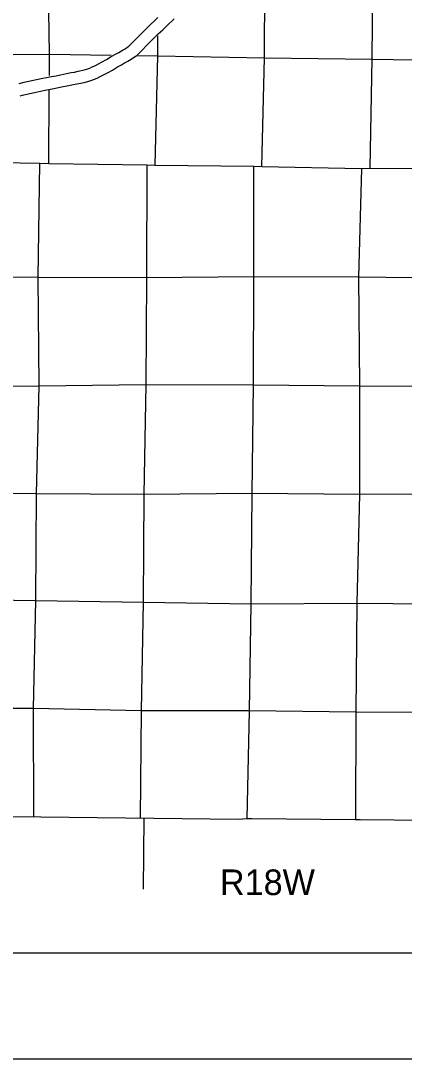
# Model space of a CAD drawing. Extents: x 369523 to 838377, y 495025 to 936819.
# Drawn here: x 611048 to 630067, y 495025 to 546526 of the extents above; entities that cross this region are included whole.
import ezdxf

# ---------------------------------------------------------------- set-up
doc = ezdxf.new("R2010")
doc.units = 0
for name, color, linetype in [('21', 7, 'Continuous'), ('Level 11', 7, 'Continuous'), ('Level 15', 7, 'Continuous'), ('Level 22', 7, 'Continuous'), ('Level 6', 7, 'Continuous')]:
    doc.layers.add(name, color=color, linetype=linetype)

msp = doc.modelspace()

# ---------------------------------------------------------------- linework, layer by layer
at = {"layer": '21'}
for p, q in [((558537, 500305), (833097, 500305)), ((838377, 495025), (542697, 495025))]:
    msp.add_line(p, q, dxfattribs=at)
at = {"layer": 'Level 11'}
for points in [[(610971, 543411), (611208, 543475), (611595, 543558), (612055, 543663), (612408, 543725), (612579, 543759), (612805, 543800), (613025, 543848), (613310, 543911), (613547, 543954), (613716, 543984), (613891, 544025), (613975, 544044), (614134, 544075), (614266, 544107), (614368, 544137), (614469, 544183), (614592, 544234), (614725, 544296), (614932, 544402), (615057, 544471), (615292, 544601), (615538, 544753), (615750, 544870), (615906, 544957), (616046, 545037), (616131, 545091), (616225, 545141), (616315, 545198), (616413, 545264), (617127, 545989), (617449, 546307), (617678, 546520), (617846, 546682)], [(611010, 542800), (611128, 542832), (611349, 542892), (611724, 542972), (612174, 543074), (612518, 543135), (612691, 543169), (612923, 543211), (613154, 543262), (613428, 543323), (613654, 543363), (613836, 543396), (614024, 543439), (614099, 543456), (614264, 543489), (614423, 543528), (614577, 543573), (614706, 543632), (614835, 543685), (614989, 543758), (615214, 543872), (615348, 543946), (615596, 544083), (615841, 544235), (616041, 544346), (616200, 544434), (616355, 544522), (616433, 544572), (616527, 544622), (616645, 544697), (616799, 544802), (617551, 545564), (617864, 545874), (618091, 546084), (618259, 546246), (618377, 546356), (618553, 546521), (618656, 546626)]]:
    msp.add_lwpolyline(points, dxfattribs=at)
at = {"layer": 'Level 15'}
msp.add_lwpolyline([(607122, 539547), (611993, 539458), (612444, 539453), (617299, 539374), (617701, 539366), (622612, 539310), (623005, 539304), (627956, 539199), (628364, 539208), (633277, 539183), (633678, 539178), (638635, 539067), (643567, 539006), (643906, 539013)], dxfattribs=at)
at = {"layer": 'Level 22'}
for points in [[(612465, 543805), (612470, 544877), (612397, 550187)], [(628509, 550007), (628463, 544630), (628364, 539208)], [(623005, 539304), (623143, 544689), (623155, 548231)], [(617826, 545782), (617824, 544783), (617701, 539366)], [(607155, 544853), (612470, 544877), (615537, 544823)], [(616856, 544800), (617824, 544783), (623143, 544689), (628463, 544630), (633774, 544542), (638683, 544393)], [(612444, 539453), (612461, 543086)], [(611693, 507058), (611671, 512414), (611803, 517767), (611826, 523059), (611956, 528418), (611916, 533786), (611993, 539458)], [(617299, 539374), (617280, 533772), (617250, 528485), (617153, 523035), (617115, 517685), (617013, 512300), (616966, 506992)], [(622282, 506962), (622390, 512304), (622474, 517614), (622525, 523083), (622593, 528465), (622606, 533833), (622612, 539310)], [(627956, 539199), (627798, 533807), (627855, 528425), (627850, 523038), (627724, 517638), (627662, 512238), (627646, 506917)], [(638581, 533778), (633207, 533747), (627798, 533807), (622606, 533833), (617280, 533772), (611916, 533786), (606590, 533853)], [(606546, 528350), (611956, 528418), (617250, 528485), (622593, 528465), (627855, 528425), (633153, 528408), (638592, 528456)], [(638496, 523156), (633068, 523058), (627850, 523038), (622525, 523083), (617153, 523035), (611826, 523059), (606522, 523094)], [(606397, 517856), (611803, 517767), (617115, 517685), (622474, 517614), (627724, 517638), (633080, 517596), (638470, 517867)], [(638454, 512581), (633091, 512216), (627662, 512238), (622390, 512304), (617013, 512300), (611671, 512414), (606422, 512411)]]:
    msp.add_lwpolyline(points, dxfattribs=at)
at = {"layer": 'Level 6'}
for points in [[(610558, 507061), (612051, 507048), (621854, 506938)], [(617140, 503454), (617166, 506991)], [(621854, 506938), (622282, 506962), (622511, 506958), (627646, 506917), (627885, 506908), (632953, 506871), (633129, 506871), (638430, 506821)]]:
    msp.add_lwpolyline(points, dxfattribs=at)

# ---------------------------------------------------------------- texts
at = {"layer": '21'}
msp.add_text('R18W', height=1267.2, dxfattribs=at).set_placement((620928, 503167))

doc.saveas('drawing.dxf')
